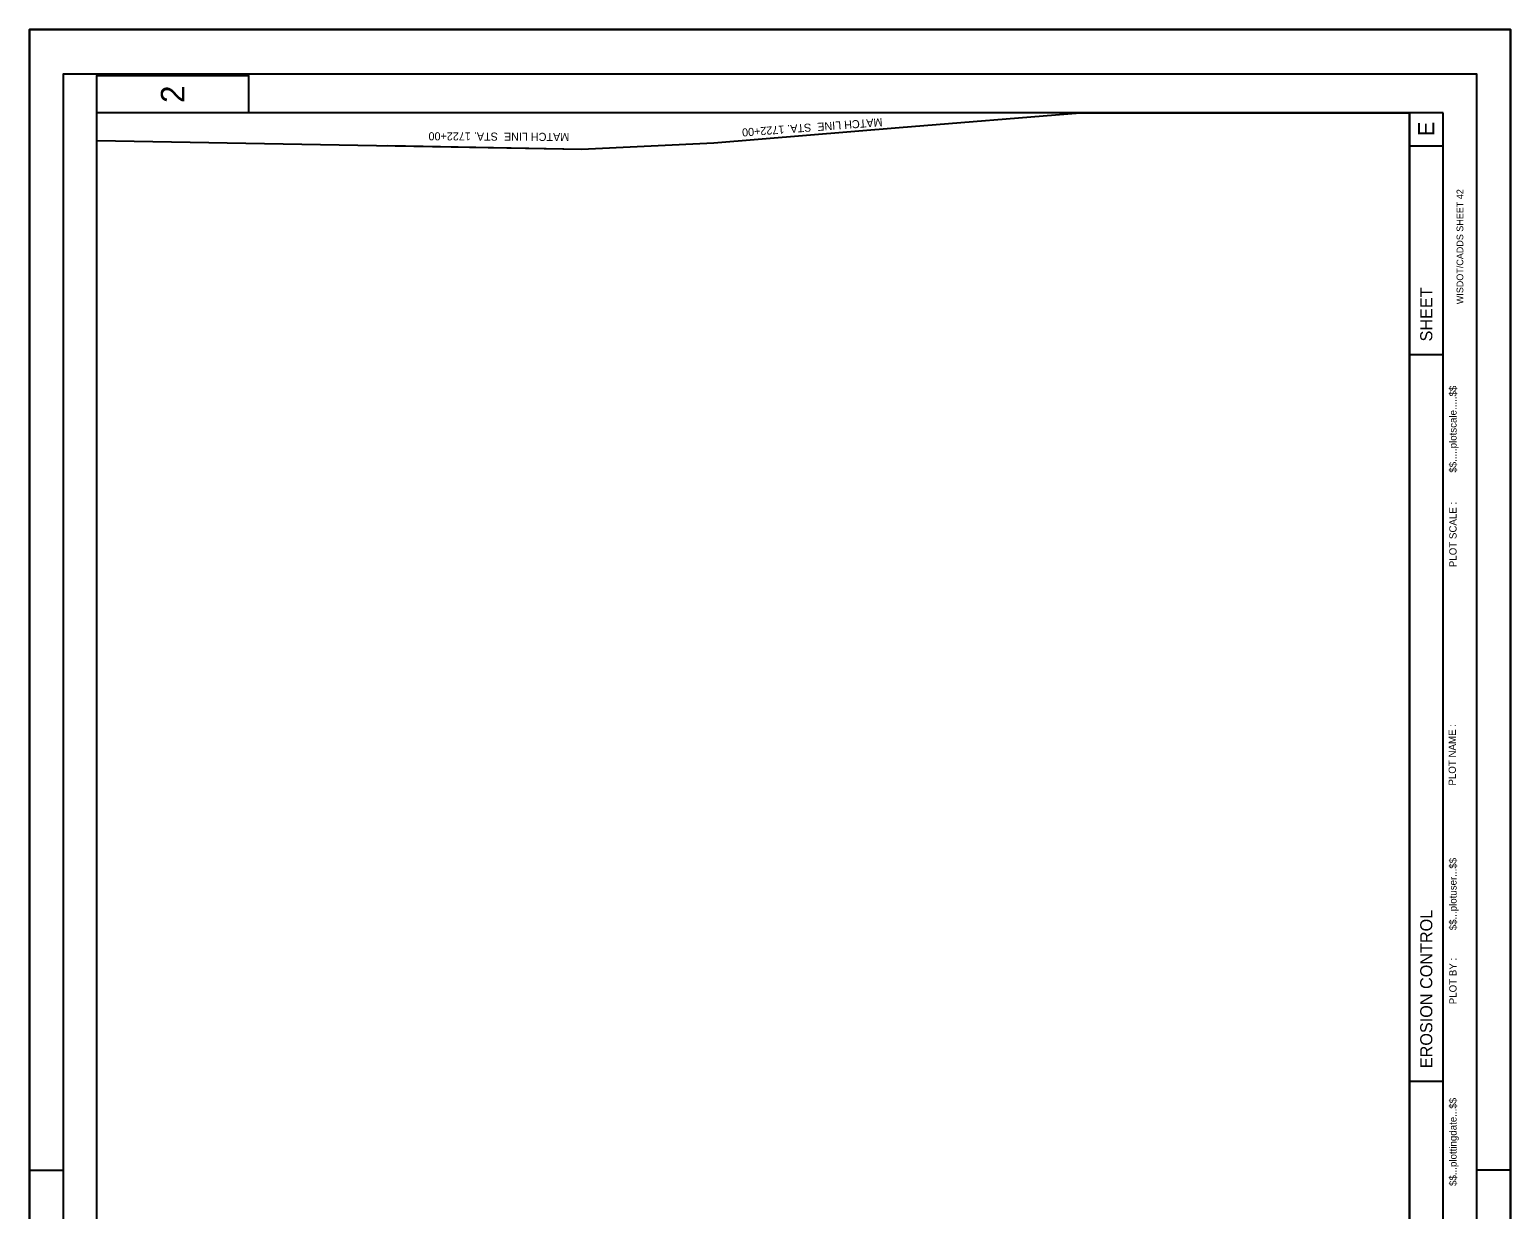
# Model space of a CAD drawing. Extents: x 361080 to 362180, y 129788 to 131488.
# Drawn here: x 361080 to 362180, y 130611 to 131488 of the extents above; entities that cross this region are included whole.
import ezdxf

# ---------------------------------------------------------------- set-up
doc = ezdxf.new("R2010")
doc.units = 0
for name, color, linetype in [('Default', 7, 'Continuous'), ('P_SHTIDX_1 [KAPUR_CADDS_LEVELS]', 7, 'Continuous'), ('P_SHTIDX_2 [KAPUR_CADDS_LEVELS]', 7, 'Continuous'), ('P_SHTIDX_3 [KAPUR_CADDS_LEVELS]', 7, 'Continuous'), ('P_TXT_Plan 2 [KAPUR_CADDS_LEVELS]', 7, 'Continuous'), ('P_TXT_Plan 3 [KAPUR_CADDS_LEVELS]', 7, 'Continuous'), ('P_TXT_Plan 4 [KAPUR_CADDS_LEVELS]', 7, 'Continuous')]:
    doc.layers.add(name, color=color, linetype=linetype)

msp = doc.modelspace()

# ---------------------------------------------------------------- linework, layer by layer
at = {"layer": 'Default'}
msp.add_lwpolyline([(361325.4, 129901.1), (361130.1, 129904.7), (361130.1, 131405.5), (361490.1, 131398.9), (361588.3, 131403.7), (361726, 131415), (361860.5, 131426.1), (362105.1, 131426.1), (362105.1, 129918.8), (361736.3, 129851.1), (361497.1, 129898)], close=True, dxfattribs=at)
msp.add_lwpolyline([(361325.4, 129901.1), (361130.1, 129904.7), (361130.1, 131405.5), (361490.1, 131398.9), (361588.3, 131403.7), (361726, 131415), (361860.5, 131426.1), (362105.1, 131426.1), (362105.1, 129918.8), (361736.3, 129851.1), (361497.1, 129898)], close=True, dxfattribs=at)
msp.add_lwpolyline([(361325.4, 129901.1), (361130.1, 129904.7), (361130.1, 131405.5), (361490.1, 131398.9), (361588.3, 131403.7), (361726, 131415), (361860.5, 131426.1), (362105.1, 131426.1), (362105.1, 129918.8), (361736.3, 129851.1), (361497.1, 129898)], close=True, dxfattribs=at)
msp.add_lwpolyline([(361325.4, 129901.1), (361130.1, 129904.7), (361130.1, 131405.5), (361490.1, 131398.9), (361588.3, 131403.7), (361726, 131415), (361860.5, 131426.1), (362105.1, 131426.1), (362105.1, 129918.8), (361736.3, 129851.1), (361497.1, 129898)], close=True, dxfattribs=at)
msp.add_lwpolyline([(361325.4, 129901.1), (361130.1, 129904.7), (361130.1, 131405.5), (361490.1, 131398.9), (361588.3, 131403.7), (361726, 131415), (361860.5, 131426.1), (362105.1, 131426.1), (362105.1, 129918.8), (361736.3, 129851.1), (361497.1, 129898)], close=True, dxfattribs=at)
msp.add_lwpolyline([(361325.4, 129901.1), (361130.1, 129904.7), (361130.1, 131405.5), (361490.1, 131398.9), (361588.3, 131403.7), (361726, 131415), (361860.5, 131426.1), (362105.1, 131426.1), (362105.1, 129918.8), (361736.3, 129851.1), (361497.1, 129898)], close=True, dxfattribs=at)
msp.add_lwpolyline([(361325.4, 129901.1), (361130.1, 129904.7), (361130.1, 131405.5), (361490.1, 131398.9), (361588.3, 131403.7), (361726, 131415), (361860.5, 131426.1), (362105.1, 131426.1), (362105.1, 129918.8), (361736.3, 129851.1), (361497.1, 129898)], close=True, dxfattribs=at)
msp.add_lwpolyline([(361325.4, 129901.1), (361130.1, 129904.7), (361130.1, 131405.5), (361490.1, 131398.9), (361588.3, 131403.7), (361726, 131415), (361860.5, 131426.1), (362105.1, 131426.1), (362105.1, 129918.8), (361736.3, 129851.1), (361497.1, 129898)], close=True, dxfattribs=at)
at = {"layer": 'P_SHTIDX_1 [KAPUR_CADDS_LEVELS]'}
msp.add_lwpolyline([(361080.1, 129787.8), (361080.1, 131487.8), (362180.1, 131487.8), (362180.1, 129787.8), (361080.1, 129787.8)], dxfattribs=at)
at = {"layer": 'P_SHTIDX_2 [KAPUR_CADDS_LEVELS]'}
for p, q in [((361130.1, 131487.8), (361080.1, 131487.8)), ((361080.1, 131437.8), (361080.1, 131487.8)), ((362180.1, 131487.8), (362130.1, 131487.8)), ((362180.1, 131437.8), (362180.1, 131487.8)), ((361130.1, 129851.1), (361130.1, 131426.1)), ((362130.1, 131426.1), (361130.1, 131426.1)), ((362105.1, 129851.1), (362105.1, 131426.1)), ((362130.1, 129851.1), (362130.1, 131426.1)), ((362130.1, 131401.1), (362105.1, 131401.1)), ((362130.1, 131246.1), (362105.1, 131246.1)), ((362130.1, 130706.1), (362105.1, 130706.1)), ((361080.1, 130615.3), (361080.1, 130665.3)), ((362180.1, 130615.3), (362180.1, 130665.3)), ((361080.1, 130640.3), (361105.1, 130640.3)), ((362180.1, 130640.3), (362155.1, 130640.3))]:
    msp.add_line(p, q, dxfattribs=at)
msp.add_lwpolyline([(361130.1, 131426.1), (361130.1, 131453.6), (361242.6, 131453.6), (361242.6, 131426.1)], close=True, dxfattribs=at)
at = {"layer": 'P_SHTIDX_3 [KAPUR_CADDS_LEVELS]'}
for points in [[(362180.1, 129787.8), (362180.1, 131487.8), (361080.1, 131487.8), (361080.1, 129787.8)], [(362155.1, 129799.8), (362155.1, 131454.8), (361105.1, 131454.8), (361105.1, 129799.8)]]:
    msp.add_lwpolyline(points, close=True, dxfattribs=at)
at = {"layer": 'P_TXT_Plan 3 [KAPUR_CADDS_LEVELS]'}
for p, q in [((361588.3, 131403.7), (361726, 131415)), ((361346.1, 131401.6), (361490.1, 131398.9))]:
    msp.add_line(p, q, dxfattribs=at)
at = {"layer": 'P_TXT_Plan 4 [KAPUR_CADDS_LEVELS]'}
msp.add_lwpolyline([(361080.1, 129787.8), (361080.1, 131487.8), (362180.1, 131487.8), (362180.1, 129787.8)], close=True, dxfattribs=at)

# ---------------------------------------------------------------- texts
at = {"layer": 'P_SHTIDX_2 [KAPUR_CADDS_LEVELS]'}
for s, height, p in [('2', 17.5, (361195.1, 131433.3)), ('E', 12, (362123.5, 131408.7)), ('WISDOT/CADDS SHEET 42', 5, (362145.1, 131283.8)), ('SHEET ', 9, (362122.1, 131256.1)), ('$$.....plotscale.....$$', 5.4, (362140.1, 131158.6)), ('PLOT SCALE : ', 5.4, (362140.1, 131088.4)), ('PLOT NAME :                      ', 5.4, (362139.6, 130926.1)), ('$$...plotuser...$$', 5.4, (362140.1, 130818.6)), ('EROSION CONTROL', 9, (362122.1, 130716.1)), ('PLOT BY :', 5.4, (362140.1, 130763.6)), ('$$...plottingdate...$$', 5.4, (362140.1, 130628.6))]:
    msp.add_text(s, height=height, rotation=90, dxfattribs=at).set_placement(p)
at = {"layer": 'P_TXT_Plan 2 [KAPUR_CADDS_LEVELS]'}
for rotation, p in [(184.2781, (361713.4, 131422.1)), (179.6776, (361481, 131411))]:
    msp.add_text('MATCH LINE  STA. 1722+00', height=6, rotation=rotation, dxfattribs=at).set_placement(p)

doc.saveas('drawing.dxf')
